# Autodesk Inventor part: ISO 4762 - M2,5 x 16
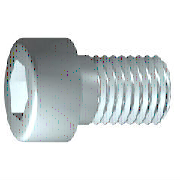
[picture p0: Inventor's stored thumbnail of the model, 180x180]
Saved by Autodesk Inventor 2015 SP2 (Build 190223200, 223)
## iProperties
Created: 2014-02
Part Number: ISO 4762 - M2,5 x 16
Material: Edelstahl, 440C
Description: Innensechskantschraube
Document SubType Name: Modeling
Standard: ISO 4762
Designer: rYan
Standard Revision: Fourth edition 2004-03-01
Standards Organization: ISO
Language: de-DE
Size Designation: M2,5 x 16
Categories: <MemberInstance><Categories><Category DisplayName="Verbindungselemente" InternalName="e4da775c-781d-43d5-af7c-5136215cf5a6" Mnemonic="FSTN"><Category DisplayNam
Density: 7.75 g/cm^3
Appearance: Halbpoliert
IsCustomPart: 0
Author: rYan
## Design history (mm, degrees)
sketch "Skizze1"
  geometry: L1 (-0.733, 0)-(16, 0); L2 (16, 0)-(16, 1.25); L3 (16, 1.25)-(1.125, 1.25); L4 (1.125, 1.25)-(0.849, 1.25); L5 (0.849, 1.25)-(0, 1.25); L6 (0, 1.25)-(0, 2.25); L7 (0, 2.25)-(-2.5, 2.25); L8 (-2.5, 2.25)-(-2.5, 1.155); L9 (-2.5, 1.155)-(-1.4, 1.155); L10 (-1.4, 1.155)-(-0.733, 0); L11 (-6.2, 0)-(19.7, 0) reference; L12 (0, -0.45)-(0, 2.7) reference; L13 (1.125, 1.25)-(0, 1.25)
  constraints: 22 end point, 6 parallel, 2 collinear, 2 perpendicular, 1 horizontal, 1 point on line
  dimensions: "d1" = 14.875 distance from line of L3.end L2 (= GEL); "d2" = 0.27615 distance of L4.end L3.end (computed from GAL); "d3" = 2.5 distance between parallel lines of L8 L6 (= KOH); "d4" = 1.1 distance of L8.end L9.end (= INTI); "d5" = 60 deg angle of L10 L1; "d6" = 2.5 diameter of L3 L1 (= GD); "d7" = 2.5 diameter of L5 L1 (= BDM); "d8" = 2.3094 diameter of L9 L1 (= 1.1547 x SW); "d9" = 4.5 diameter of L7 L1 (= KOD); "d26" = 16 distance between parallel lines of L12 L2 (= NLG)
revolve "Körper" sketch "Skizze1" stored, may be unused: angle "d10" = 90 deg
sketch "Skizze2"
  geometry: L1 (0, -3.15)-(0, 3.15) reference; L2 (-3.15, 0)-(3.15, 0) reference; L3 (1.155, 0)-(0.577, -1); L4 (0.577, -1)-(-0.577, -1); L5 (-0.577, -1)-(-1.155, 0); L6 (-1.155, 0)-(-0.577, 1); L7 (-0.577, 1)-(0.577, 1); L8 (0.577, 1)-(1.155, 0); 2 further points
  constraints: 12 end point, 1 coincident, 1 horizontal alignment, 1 point on line, 12 other
extrude "Loch" join sketch "Skizze2" stored distance "d11" = 10; taper "d12" = 0 deg
workplane "Work Plane1"
fillet "Fillet2" dims "d30" = 0.1 (= R)
body "Solid1"
fillet "Rundung1" dims "d17" = 0.25 (= RR)
feature "Gewinde" dims "d13" = 14.875 (= GEL), "d14" = 0
chamfer "Fase1" distance "d15" = 0.27605 (= -0.5 x SPD + 0.5 x GD); stored, may be unused: second distance "d16" = 0.27605 (= GUL), angle "d27" = 45 deg
other parameters: "GD" = 2.5 [user parameter; used in 2 equation terms], "NLG" = 16 [user parameter; used in 1 equation term], "GEL" = 14.875 [user parameter; used in 2 equation terms], "KOD" = 4.5 [user parameter; used in 1 equation term], "KOH" = 2.5 [user parameter; used in 1 equation term], "INTI" = 1.1 [user parameter; used in 1 equation term], "GAL" = 0.27605 (= 0.61345 x PTC) [user parameter; used in 1 equation term], "GUL" = 0.27605 (= 0.61345 x PTC) [user parameter; used in 1 equation term], "BDM" = 2.5 (= NND) [user parameter; used in 1 equation term], "SW" = 2 [user parameter; used in 2 equation terms], "RR" = 0.25 [user parameter; used in 1 equation term], "SPD" = 1.94789 (= NND - 1.2269 x PTC) [user parameter; used in 1 equation term], "d19" = 0, "d28" = 0, "d29" = 0, "R" = 0.1 [user parameter; used in 1 equation term], "TOA" = 30 deg [user parameter], "GD1" = 1.94789 (= THREADDIA - 1.2269 x PTC) [user parameter], "THREADDIA" = 2.5 [user parameter; used in 1 equation term], "FAWI" = 45 deg [user parameter], "TPU" = 22.22222 (computed from PTC) [user parameter], "PTC" = 0.45 [user parameter; used in 5 equation terms], "NND" = 2.5 [user parameter; used in 2 equation terms], "E0" = 2.31 (= 1.155 x SW) [user parameter]
